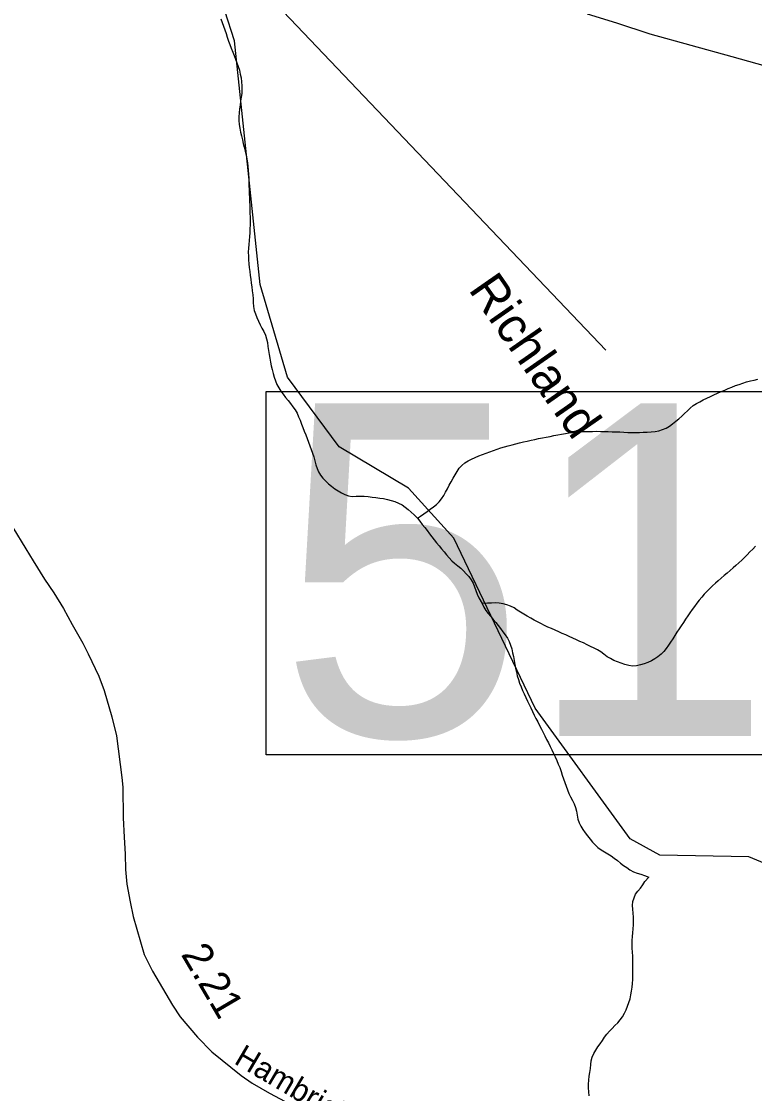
# Model space of a CAD drawing. Extents: x 1950930 to 2061844, y 904556 to 1017002.
# Drawn here: x 1970280 to 1973365, y 965651 to 970163 of the extents above; entities that cross this region are included whole.
import ezdxf

# ---------------------------------------------------------------- set-up
doc = ezdxf.new("R2010")
doc.units = 0
for name, color, linetype in [('Exist Hydrographic Creek Single Shore', 7, 'Continuous'), ('Exist Hydrographic Creek Single Shore Label', 7, 'Continuous'), ('Exist Hydrographic Misc Water Feature', 7, 'Continuous'), ('Exist Road Primary US Structure Standard Bridge CELL', 7, 'Continuous'), ('Exist Road Secondary Mileage Hundredths English Label', 7, 'Continuous'), ('Exist Road Secondary Structure Standard Bridge Number Label', 7, 'Continuous'), ('Exist Road Secondary Type 51 Attributed', 7, 'Continuous'), ('Exist Road Secondary Type 51 Label', 7, 'Continuous')]:
    doc.layers.add(name, color=color, linetype=linetype)

msp = doc.modelspace()

# ---------------------------------------------------------------- linework, layer by layer
at = {"layer": 'Exist Hydrographic Creek Single Shore'}
msp.add_lwpolyline([(1974840.4, 965513.3), (1974682.3, 965746.3), (1974549.2, 966054.4), (1974116.4, 966562.2), (1974033.3, 966586.8), (1973866.4, 966547.6), (1973741.3, 966330.2), (1973666.3, 966348.2), (1973466.4, 966595.3), (1973341.3, 966647.1), (1972966.2, 966654.8), (1972841.4, 966723), (1972441.3, 967272.9), (1972100.3, 967988.8), (1971909.4, 968199.5), (1971617.4, 968373), (1971400.2, 968666.4), (1971284.4, 969056.1), (1971176.3, 970082.3), (1971135.3, 970207.9)], dxfattribs=at)
at = {"layer": 'Exist Hydrographic Misc Water Feature'}
for points in [[(1971118.5, 970174.2), (1971124.1, 970158.5), (1971129.8, 970142.7), (1971135.3, 970127.9), (1971140.7, 970112.2), (1971146, 970096.5), (1971151.5, 970080.7), (1971157.1, 970065.8), (1971162.8, 970050.1), (1971168.8, 970034.5), (1971174.7, 970019.6), (1971181.1, 970004.7), (1971186.8, 969989), (1971192.1, 969973.2), (1971196.8, 969957.6), (1971200.5, 969942), (1971204, 969925.5), (1971206.1, 969909), (1971207.5, 969892.6), (1971207.5, 969877), (1971206.7, 969860.6), (1971204.6, 969844.2), (1971202.2, 969827.8), (1971199.9, 969811.5), (1971197.5, 969795.2), (1971195.6, 969778.8), (1971194.8, 969762.4), (1971195, 969745.9), (1971196.4, 969729.4), (1971198.9, 969713.9), (1971202, 969697.4), (1971205.5, 969681.8), (1971209.6, 969665.3), (1971213.5, 969649.6), (1971217.6, 969633.9), (1971221.7, 969617.4), (1971225.3, 969601.7), (1971228.6, 969585.2), (1971231.1, 969568.8), (1971232.9, 969553.2), (1971234.6, 969536.7), (1971235.4, 969520.3), (1971236.2, 969503.9), (1971236.6, 969487.4), (1971237, 969471), (1971237.7, 969454.6), (1971238.7, 969438.2), (1971239.5, 969421.8), (1971239.9, 969405.3), (1971240.5, 969389), (1971240.9, 969372.4), (1971241.3, 969356)], [(1971241.3, 969356), (1971241.8, 969339.6), (1971241.8, 969323.2), (1971242, 969306.8), (1971241.5, 969290.4), (1971240.5, 969274), (1971239.3, 969257.6), (1971237.7, 969241.3), (1971236.2, 969224.9), (1971234.8, 969208.5), (1971234.6, 969192.1), (1971234.8, 969175.7), (1971236, 969159.2), (1971237.2, 969142.8), (1971238.7, 969127.2), (1971240.7, 969110.7), (1971242.6, 969094.3), (1971244.8, 969077.9), (1971246.9, 969061.4), (1971248.9, 969045.7), (1971251.2, 969029.3), (1971253, 969012.9), (1971254.7, 968996.4), (1971255.5, 968980), (1971256.3, 968963.6), (1971259.2, 968947.1), (1971264.5, 968932.2), (1971270.7, 968917.2), (1971277.8, 968901.5), (1971284.8, 968886.7), (1971291.8, 968871.7), (1971299.6, 968857.7), (1971306.3, 968842.7), (1971311.5, 968827), (1971314.7, 968811.3), (1971317.4, 968794.9), (1971319.7, 968778.4), (1971322.1, 968762), (1971324.6, 968746.3), (1971327.7, 968729.8), (1971331.4, 968714.2), (1971335.1, 968697.7), (1971339.2, 968682), (1971343.7, 968665.5), (1971348.8, 968650.7), (1971355.1, 968635), (1971362.5, 968620.8), (1971371.3, 968607.5), (1971381, 968594.2), (1971391.4, 968580.8), (1971401.7, 968568.3), (1971411.9, 968555), (1971421.8, 968541.7), (1971431.8, 968529.2), (1971439.8, 968514.2), (1971446.2, 968499.3), (1971452.3, 968484.4), (1971458.3, 968468.7), (1971464.4, 968453.8), (1971470.2, 968438.1), (1971476.1, 968423.2), (1971481.9, 968407.5), (1971487.4, 968392.6), (1971493.4, 968376.9), (1971499.1, 968361.2), (1971504.8, 968346.4), (1971510.2, 968330.6), (1971514.5, 968314.1), (1971518.8, 968297.6), (1971523.9, 968281.9), (1971530.1, 968267), (1971538.3, 968253.7), (1971548.3, 968241.2), (1971559.6, 968229.5), (1971571.9, 968217.8), (1971585, 968206.8), (1971598.5, 968196.7), (1971612.5, 968187.3), (1971626.8, 968178.8), (1971641.2, 968172), (1971655.8, 968166.7), (1971672, 968164), (1971688.6, 968164.5), (1971705.6, 968164.9), (1971722.4, 968164.6), (1971738.8, 968163.4), (1971755.2, 968161.4), (1971771.4, 968159.5), (1971787.8, 968157.4), (1971803.8, 968154.7), (1971820, 968151.1), (1971836.2, 968146.6), (1971851.8, 968142.2), (1971867, 968136.1), (1971881.5, 968128.4), (1971895, 968119.2), (1971907.8, 968109.1), (1971920.1, 968098.1), (1971932.2, 968086.4), (1971946.3, 968072.1)], [(1971946.3, 968072.1), (1971959.6, 968081.7), (1971973.2, 968091.3), (1971986.9, 968100.8), (1972000.4, 968110.4), (1972013.8, 968120), (1972026.3, 968130.3), (1972038, 968141.6), (1972048.4, 968153.7), (1972057.2, 968167.6), (1972065, 968182.1), (1972072.6, 968196.7), (1972080.2, 968211.3), (1972088.6, 968225.9), (1972096.8, 968240.6), (1972105, 968255.1), (1972113.4, 968268.9), (1972122.7, 968282.6), (1972133.1, 968294.8), (1972145.4, 968305.2), (1972159.4, 968313.9), (1972174.3, 968320.9), (1972189.7, 968328), (1972204.7, 968334.3), (1972220.1, 968340.5), (1972235.4, 968346.8), (1972250.6, 968352.2), (1972266.2, 968357.6), (1972281.6, 968363), (1972297.2, 968368.4), (1972312.9, 968373.1), (1972328.9, 968377.6), (1972344.5, 968381.4), (1972360.3, 968386), (1972376.5, 968389.8), (1972392.3, 968393.6), (1972408.5, 968397.3), (1972424.5, 968400.3), (1972440.7, 968404.1), (1972456.7, 968407.9), (1972472.7, 968410.8), (1972488.7, 968413.7), (1972504.9, 968416.7), (1972520.9, 968420.5), (1972537.3, 968423.4), (1972553.3, 968426.3), (1972569.5, 968429.3), (1972585.7, 968432.2), (1972602.1, 968434.3), (1972618.3, 968435.7), (1972634.7, 968437), (1972650.9, 968437.5), (1972667.3, 968437.9), (1972683.7, 968437.6), (1972700.1, 968438.1), (1972716.5, 968437.7), (1972733.1, 968437.4), (1972749.3, 968437.1), (1972765.7, 968435.9), (1972782.1, 968435.6), (1972798.7, 968435.3), (1972815.1, 968434.1), (1972831.5, 968433.7), (1972847.9, 968433.4), (1972864.3, 968433.8), (1972880.7, 968433.5), (1972897.1, 968434), (1972913.5, 968434.4), (1972930.2, 968435.8), (1972946.8, 968437.9), (1972963, 968440.8), (1972978.5, 968445.5), (1972993.1, 968451.8), (1973007, 968460.5), (1973020.4, 968470), (1973033.5, 968480.4), (1973046.4, 968490.8), (1973058.9, 968501.2), (1973070.8, 968513.3), (1973082.9, 968524.6), (1973095, 968535.8), (1973107.5, 968546.2), (1973121.3, 968554.9), (1973135.4, 968562.8), (1973149.6, 968570.7), (1973164.3, 968577.8), (1973179.3, 968584.9), (1973194.1, 968592), (1973209.2, 968598.3), (1973224.6, 968605.2), (1973239.8, 968611.5), (1973255, 968617.8), (1973270.1, 968624), (1973285.3, 968630.3), (1973300.7, 968635.7), (1973316.3, 968641.1), (1973332.1, 968646.6), (1973347.8, 968651.2), (1973363.6, 968654.1), (1973379.8, 968657)], [(1971946.3, 968072.1), (1971956.6, 968059.6), (1971966.8, 968046.3), (1971977.1, 968033.8), (1971986.9, 968020.4), (1971997, 968007.1), (1972007.2, 967994.6), (1972017.3, 967981.3), (1972027.3, 967968.8), (1972037.8, 967956.2), (1972047.8, 967942.9), (1972058.3, 967930.3), (1972068.9, 967917.8), (1972079.6, 967905.3), (1972090.7, 967893.6), (1972103, 967882.6), (1972116.1, 967872.5), (1972128.8, 967862.4), (1972140.9, 967851.5), (1972152, 967839), (1972162.4, 967826.5), (1972172.1, 967813.1), (1972180.7, 967799), (1972187, 967784.1), (1972192, 967768.4), (1972197.3, 967752.6), (1972204.7, 967737.8), (1972218.4, 967712.9)], [(1973369.2, 967954.1), (1973357.5, 967942.8), (1973346, 967930.7), (1973334.9, 967918.7), (1973323.4, 967907.5), (1973311.5, 967896.2), (1973299.4, 967885), (1973286.9, 967873.7), (1973274.8, 967863.4), (1973262.1, 967852.9), (1973249.8, 967841.7), (1973237.5, 967831.3), (1973225.4, 967820), (1973212.9, 967808.8), (1973200.8, 967798.4), (1973188.7, 967787.1), (1973176.8, 967775.9), (1973164.9, 967763.9), (1973153.9, 967752.5), (1973143.2, 967739.7), (1973132.5, 967727.6), (1973122.7, 967714.7), (1973112.9, 967701), (1973103.2, 967688), (1973093.4, 967674.3), (1973084.1, 967661.3), (1973074.7, 967647.5), (1973065.9, 967633.8), (1973056.7, 967620.1), (1973047.9, 967606.2), (1973038.8, 967592.5), (1973029.8, 967578.8), (1973021.2, 967565), (1973012.2, 967551.3), (1973003.4, 967537.4), (1972993.9, 967523.7), (1972983.5, 967511.6), (1972971.8, 967499.6), (1972958.9, 967489.1), (1972945.5, 967480.3), (1972931.2, 967471.7), (1972916.2, 967464.5), (1972900.8, 967459.2), (1972884.8, 967455.4), (1972868.2, 967451.6), (1972851.8, 967450.3), (1972835.8, 967452.3), (1972820, 967456.7), (1972804.5, 967462), (1972789.1, 967468), (1972773.7, 967474.1), (1972758.9, 967481.8), (1972744.8, 967489.5), (1972731.5, 967499.6), (1972718.3, 967509.7), (1972704.6, 967518.2), (1972689.8, 967525.8), (1972675.3, 967532.7), (1972660.3, 967539.6), (1972645.5, 967547.3), (1972630.6, 967553.3), (1972615.8, 967560.3), (1972600.8, 967567.2), (1972585.7, 967574), (1972570.9, 967580.9), (1972555.7, 967587.8), (1972541, 967594.6), (1972525.8, 967601.5), (1972510.8, 967607.6), (1972495.8, 967614.4), (1972481.1, 967621.3), (1972466.3, 967629), (1972451.8, 967635.9), (1972437.4, 967643.5), (1972423.1, 967652), (1972408.5, 967659.6), (1972394.3, 967668.2), (1972380.6, 967676.7), (1972366.9, 967686), (1972353.1, 967695.3)], [(1972353.1, 967695.3), (1972338.6, 967702.2), (1972323, 967707.4), (1972306.8, 967711.8), (1972290.8, 967714.7), (1972274.4, 967715.8), (1972257.8, 967715.3), (1972241.6, 967714.9), (1972218.4, 967712.9)], [(1972218.4, 967712.9), (1972225.6, 967697.9), (1972234.2, 967683.8), (1972244, 967671.3), (1972254.7, 967658.8), (1972265.4, 967646.2), (1972275.8, 967633.7), (1972286.3, 967620.4), (1972296.1, 967607.9), (1972306.2, 967594.5), (1972316.2, 967581.2), (1972325.2, 967567.1), (1972332.8, 967553), (1972338.6, 967538.1), (1972343.3, 967522.4), (1972347.2, 967506), (1972350.7, 967490.3), (1972353.5, 967473.8), (1972356.6, 967457.3), (1972359.7, 967441.6), (1972363.2, 967425.2), (1972366.9, 967409.5), (1972371.2, 967393.8), (1972376.7, 967378.1), (1972382.7, 967363.2), (1972389, 967347.5), (1972395.6, 967332.6), (1972402.3, 967317.7), (1972409.1, 967302.8), (1972416.3, 967287.9), (1972423.5, 967273.7), (1972430.6, 967258.9), (1972437.8, 967243.9), (1972445.4, 967229), (1972452.8, 967214.9), (1972460.4, 967200), (1972468, 967185.1), (1972475.3, 967170.9), (1972482.9, 967156), (1972490.1, 967141.1), (1972497.7, 967127), (1972504.9, 967112.2), (1972512, 967097.2), (1972519.2, 967082.2), (1972526.2, 967067.4), (1972532.8, 967052.4), (1972539.3, 967037.5), (1972545.5, 967022.7), (1972550.8, 967007), (1972556.1, 966991.3), (1972561.5, 966975.6), (1972566.6, 966959.9), (1972571.9, 966944.9), (1972577.9, 966929.3), (1972584.2, 966914.4), (1972591.4, 966899.4), (1972598.6, 966884.4), (1972605.6, 966869.6), (1972611.7, 966854.7), (1972616.4, 966839), (1972619.3, 966822.5), (1972622.2, 966806), (1972627.1, 966790.3), (1972634.7, 966776.3), (1972643.3, 966762.1), (1972652.7, 966748.8), (1972662.6, 966735.5), (1972672.8, 966722.1), (1972683.7, 966709.6), (1972695, 966698), (1972706.4, 966687), (1972719.6, 966676.8), (1972733.7, 966668.4), (1972748.1, 966659.8), (1972762, 966651.4), (1972775.1, 966641.3), (1972788.3, 966631.2), (1972801.2, 966621.1), (1972814.1, 966610.9), (1972827.4, 966601.6), (1972841, 966592.2), (1972855.3, 966584.7), (1972870.7, 966578.6), (1972886.5, 966574.2), (1972902.1, 966568.9), (1972920.9, 966561.1)], [(1972668.9, 965641.6), (1972667.9, 965658), (1972666.5, 965674.5), (1972666.5, 965690.8), (1972667.9, 965707.3), (1972669.9, 965723.6), (1972672.4, 965740.1), (1972674.7, 965756.4), (1972675.7, 965772.8), (1972677.7, 965789.2), (1972681.4, 965804.6), (1972688.4, 965819.3), (1972696.8, 965833.9), (1972706.2, 965847.6), (1972715.5, 965860.6), (1972724.9, 965874.4), (1972734.3, 965888.1), (1972744.2, 965901), (1972754.8, 965913.9), (1972766.1, 965925.1), (1972777.8, 965937.2), (1972789.5, 965948.5), (1972800.4, 965960.6), (1972809.6, 965974.3), (1972817.6, 965988.9), (1972824.8, 966003.5), (1972831.3, 966018.9), (1972836.9, 966034.5), (1972841.2, 966050), (1972844.8, 966066.3), (1972848.1, 966081.9), (1972850.6, 966098.2), (1972851.8, 966114.6), (1972852.6, 966131), (1972853.1, 966147.3), (1972853.3, 966163.8), (1972853.5, 966180.2), (1972853.5, 966196.6), (1972853.1, 966213), (1972852.6, 966229.4), (1972851.8, 966245.8), (1972850.8, 966262.3), (1972850.4, 966278.7), (1972850.8, 966295.1), (1972851.8, 966311.4), (1972853.3, 966327.8), (1972854.5, 966344.2), (1972855.5, 966360.6), (1972855.9, 966377), (1972855.3, 966393.4), (1972854.5, 966410), (1972853.1, 966426.4), (1972852.2, 966442.8), (1972853.7, 966459.2), (1972858, 966474.7), (1972864.7, 966490.1), (1972874, 966503), (1972884.8, 966515.9), (1972895.1, 966528.9), (1972903.1, 966543.4), (1972920.9, 966561.1)]]:
    msp.add_lwpolyline(points, dxfattribs=at)
at = {"layer": 'Exist Road Secondary Mileage Hundredths English Label'}
msp.add_line((1970994.5, 970612.5), (1972739.4, 968780.3), dxfattribs=at)
at = {"layer": 'Exist Road Secondary Structure Standard Bridge Number Label'}
msp.add_lwpolyline([(1971309.9, 968605.6), (1973886.4, 968605.6), (1973886.4, 967076.4), (1971309.9, 967076.4)], close=True, dxfattribs=at)
at = {"layer": 'Exist Road Secondary Type 51 Attributed'}
for points in [[(1972660.2, 970195.3), (1972784.4, 970156.8), (1972924.4, 970111.2), (1973097.7, 970063.9), (1973270.1, 970015.8), (1973410.5, 969975.9), (1973744.8, 969886.6), (1973904.1, 969842.8), (1974035.1, 969803.6), (1974228.9, 969748), (1974454.7, 969688.4), (1974614, 969637.6), (1974731.7, 969606.5), (1974826.2, 969575.9), (1974930.3, 969542.6), (1975031.8, 969524.2), (1975187.1, 969483.5)], [(1970243.5, 968032.9), (1970297.7, 967944), (1970329.7, 967893.3), (1970377.2, 967815.6), (1970415.5, 967758.7), (1970456.4, 967692.9), (1970493.3, 967624.9), (1970538.6, 967546.6), (1970560.8, 967501.3), (1970604.8, 967407.5), (1970628, 967347), (1970660.8, 967235.9), (1970680.4, 967155.9), (1970702.6, 966980.8), (1970706.2, 966940.8), (1970708.4, 966811.4), (1970712, 966729.6), (1970716.4, 966658.5), (1970717.7, 966593.2), (1970723.1, 966532.7), (1970737.3, 966458), (1970750.6, 966396.7), (1970796.4, 966236.2), (1970831.1, 966166), (1970915.1, 966022.4), (1970947.1, 965974.4), (1971021.3, 965887.7), (1971080.9, 965826.4), (1971204.2, 965727.2), (1971251.1, 965694.4), (1971324, 965652.6), (1971845, 965374.3)]]:
    msp.add_lwpolyline(points, dxfattribs=at)

# ---------------------------------------------------------------- texts
at = {"layer": 'Exist Hydrographic Creek Single Shore Label'}
msp.add_text('Richland', height=150, rotation=304.8608, dxfattribs=at).set_placement((1972158.3, 969035))
msp.add_text('Richland', height=150, rotation=304.8608, dxfattribs=at).set_placement((1972158.3, 969035))
msp.add_text('Richland', height=150, rotation=304.8608, dxfattribs=at).set_placement((1972158.3, 969035))
at = {"layer": 'Exist Road Primary US Structure Standard Bridge CELL'}
msp.add_text('2.21', height=125, rotation=300.4201, dxfattribs=at).set_placement((1970949, 966237))
at = {"layer": 'Exist Road Secondary Structure Standard Bridge Number Label'}
msp.add_text('51', height=1400, dxfattribs=at).set_placement((1971360.1, 967155.5))
at = {"layer": 'Exist Road Secondary Type 51 Label'}
msp.add_text('Hambrick Rd.', height=95, rotation=329.4999, dxfattribs=at).set_placement((1971170.2, 965779.7))

doc.saveas('drawing.dxf')
